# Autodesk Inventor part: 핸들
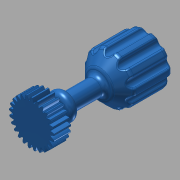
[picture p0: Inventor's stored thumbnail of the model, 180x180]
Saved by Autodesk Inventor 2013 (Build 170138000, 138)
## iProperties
Created: 2017-04
Part Number: 핸들
Material: 강철, 연강
Document SubType Name: Modeling
Designer: mduedu
Categories: <?xml version="1.0" encoding="UTF-16"?> <MemberInstance><Categories><FamilyTemplate><FamilyTemplateParameter ValueType="xs:double" Id="1" ObjectReferenceKey="da
Density: 7.86 g/cm^3
Mass: 193.546 g
Surface Area: 74.53 cm^2
Volume: 24.6242 cm^3
CustomPartVersion: 1
Author: mduedu
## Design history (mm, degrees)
sketch "Sketch1"
  geometry: C1 r 13.5 at (0, 0)
  constraints: 1 centre point
  dimensions: "d0" = 27 diameter of C1 (= da_da)
extrude "Extrusion1" new body sketch "Sketch1" distance "d1" = 10 (= da_b); taper "d2" = 0 deg
workplane "Work Plane2"
sketch "Sketch2"
  geometry: C1 r 13.5 at (0, 0) reference; C2 r 12.5 at (0, 0)
  constraints: 1 centre point, 1 coincident
  dimensions: "d3" = 25 diameter of C2 (= da_dw)
feature "피치 지름" sketch "Sketch2" dims "d4" = 10, "d5" = 0
workplane "Work Plane8"
workplane "Work Plane9"
feature "스퍼 기어" dims "da_b" = 10, "da_d" = 25, "da_aw" = 25, "da_da" = 27, "da_df" = 22.5, "da_dw" = 25, angle "da_beta" = 0 deg, "da_lefttooth" = 0, "da_righttooth" = 0
sketch "스케치3"
  geometry: C1 r 5 at (0, 0); 1 further point
  constraints: 1 centre point, 1 coincident
  dimensions: "d49" = 10 diameter of C1
extrude "돌출2" join sketch "스케치3" distance "d50" = 60; taper "d51" = 0 deg
sketch "스케치4"
  geometry: C1 r 15 at (0, 0); 1 further point
  constraints: 1 centre point, 1 coincident
  dimensions: "d52" = 30 diameter of C1
extrude "돌출3" join sketch "스케치4" distance "d53" = 30; taper "d54" = 0 deg
chamfer "모따기1" distance "d55" = 7; stored, may be unused: second distance "d56" = 2, angle "d57" = 45 deg
sketch "스케치5"
  geometry: L1 (0, 2.2)-(0, -13.2) reference; L2 (0, -5)-(8, -5); L3 (8, -5)-(8, -11); L4 (8, -11)-(0, -11); L5 (0, -11)-(0, -5); 1 further point
  constraints: 8 end point, 2 parallel, 1 horizontal, 1 perpendicular, 1 point on line
  dimensions: "d58" = 5 distance from line of L2 point (0, 0); "d59" = 6 distance of L2.end L3.end; "d60" = 16 diameter of L3 L1
revolve "회전1" sketch "스케치5" stored, may be unused: angle "d61" = 90 deg
fillet "모깎기1" dims "d62" = 3
fillet "모깎기2" dims "d65" = 3
fillet "모깎기3" dims "d72" = 3
sketch "스케치6"
  geometry: C1 r 2.5 at (0, 15); 2 further points
  constraints: 2 vertical alignment, 1 centre point, 1 other
  dimensions: "d66" = 5 diameter of C1
extrude "돌출4" cut sketch "스케치6" stored distance "d67" = 35; taper "d68" = 0 deg
fillet "모깎기4" dims "d73" = 1
body "Solid1"
pattern_circular "원형 패턴2" dims angle "d75" = 360 deg
body "Srf1"
other parameters: "d16" = 25 (= da_aw), "d17" = 0, "d34" = 1.25664 (computed from da_z), "d39" = 0, "d41" = 0, "d43" = 25 (= da_aw), "d46" = 25 (= da_aw), "d47" = 0, "d48" = 0
